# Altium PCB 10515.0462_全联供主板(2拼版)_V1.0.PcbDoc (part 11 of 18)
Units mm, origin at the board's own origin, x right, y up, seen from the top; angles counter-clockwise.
Board outline 282 x 198 mm, 2 copper layers (Top Layer, Bottom Layer); 716 components, 0 nets, 2364 pads, 1800 vias.
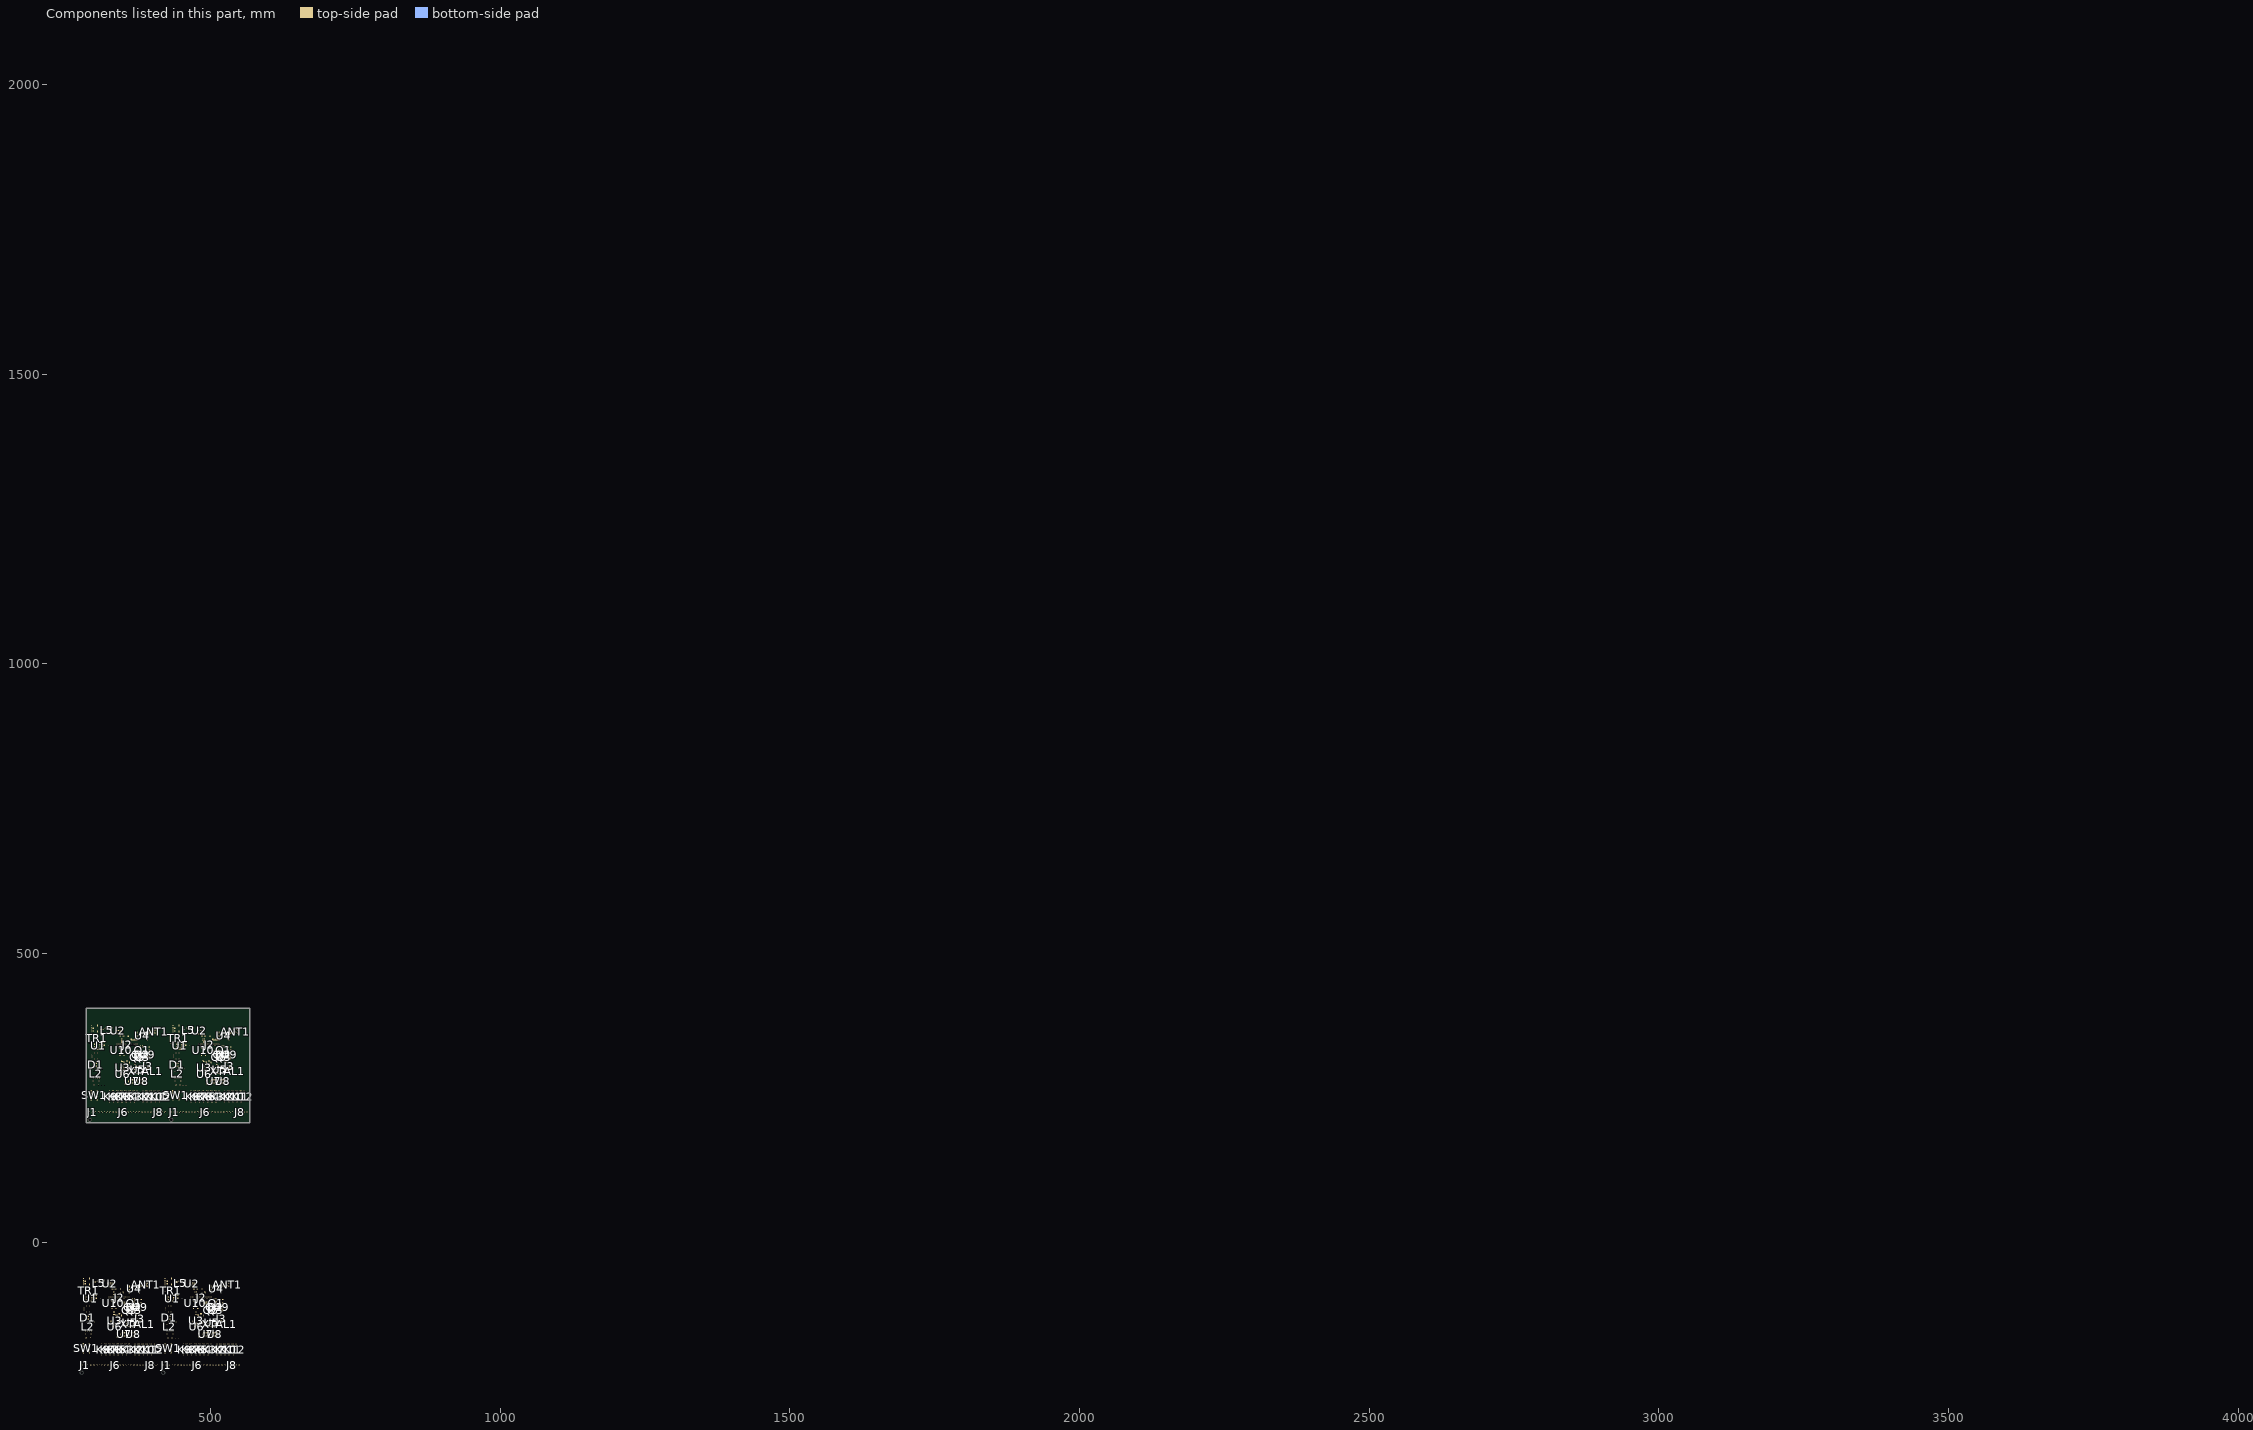
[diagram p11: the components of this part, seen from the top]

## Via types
v1: diameter 0.7, hole 0.4, Top Layer to Bottom Layer, tented both sides, 1800 vias

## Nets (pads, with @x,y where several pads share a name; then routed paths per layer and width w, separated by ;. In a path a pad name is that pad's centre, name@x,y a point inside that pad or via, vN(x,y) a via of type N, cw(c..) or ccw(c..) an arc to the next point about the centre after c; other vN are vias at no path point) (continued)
copper on no net: (continued)
  Top Layer w0.65: 500.638,-117.091 cw(c499.89,-117.091) 500.419,-117.621 cw(c500.948,-118.15) 500.948,-117.401 ; 500.684,353.257 v1@499.668,354.273 ; 501.094,331.277 501.094,334.654 ; 501.758,-118.909 503.917,-118.909 503.917,-119.63 504.327,-120.041 v1(504.581,-120.041) ; 501.758,-109.765 501.758,-112.781 501.948,-112.972 501.948,-114.591 ; 501.76,-112.861 cw(c501.307,-113.315) 501.948,-113.315 ; 501.774,-114.354 ccw(c501.353,-113.933) 501.948,-113.933 ccw(c502.543,-113.933) 502.122,-114.354 ; 502.031,350.209 ccw(c502.031,351.385) 502.862,350.554 ; v1(502.081,308.486) 502.081,311.855 501.674,312.262 500.607,312.262 ; 502.081,311.093 500.912,312.262 500.607,312.262 ; 502.22,352.432 cw(c502.22,351.523) 502.862,352.166 ; 502.373,353.346 cw(c501.251,352.223) 502.838,352.223 ; 502.462,350.534 502.92,350.534 ; 502.745,334.654 v1(503.589,334.654) ; 502.84,350.514 cw(c502.462,350.597) 502.462,350.209 500.43,350.209 ; 503.279,-107.306 ccw(c502.553,-106.58) 503.579,-106.58 ccw(c504.605,-106.58) 503.88,-107.306 ccw(c504.605,-106.58) 504.605,-107.606 ccw(c504.605,-108.632) 503.88,-107.907 ; 503.679,-112.797 cw(c503.258,-113.218) 503.853,-113.218 cw(c504.448,-113.218) 504.027,-112.797 ; 503.73,-105.271 cw(c505.343,-106.884) 505.343,-104.603 ; 503.853,-114.528 503.853,-112.559 ; 504.105,-119.819 ccw(c504.581,-119.342) v1@504.581,-120.016 ; 504.29,352.14 504.772,352.622 508.609,352.622 509.016,352.216 ; 504.347,352.12 cw(c505.56,350.908) 505.56,352.622 ; 504.581,-128.806 v1(504.581,-127.28) ; 504.61,331.32 504.61,334.654 ; 504.634,-109.84 ccw(c504.105,-109.311) 504.853,-109.311 ccw(c505.601,-109.311) 505.072,-109.84 ; 504.853,-110.059 504.853,-107.749 ; 505.343,-103.658 503.579,-105.422 503.579,-107.606 506.246,-107.606 ; 505.568,-116.75 505.568,-118.909 507.854,-118.909 ; 505.708,350.534 501.319,350.534 ; 505.789,350.616 503.002,350.616 502.92,350.534 ; 505.946,-107.907 ccw(c505.22,-108.632) 505.22,-107.606 ccw(c505.22,-106.58) 505.946,-107.306 ; v1(506.291,-128.11) 507.107,-127.294 v1(507.107,-126.264) ; v1(507.121,-101.118) 508.201,-101.118 ; 507.87,-112.797 cw(c507.449,-113.218) 508.044,-113.218 cw(c508.639,-113.218) 508.218,-112.797 ; 507.93,352.622 cw(c507.93,351.169) 508.958,352.197 ; 508.044,-112.559 508.044,-113.631 509.044,-114.631 511.623,-114.631 511.727,-114.528 ; 508.079,331.277 508.079,334.654 ; 508.137,-102.039 ccw(c509.012,-102.039) 508.393,-102.658 ; 508.137,-101.118 508.137,-102.814 508.219,-102.896 ; 508.734,-114.631 ccw(c507.986,-114.631) 508.515,-114.102 ccw(c509.044,-113.573) 509.044,-114.321 ; 508.95,-105.615 cw(c507.198,-107.367) 509.675,-107.367 ; 509.073,352.197 cw(c509.723,351.548) 509.723,352.465 ; 509.169,-105.396 509.675,-105.902 509.675,-107.606 ; 509.263,-114.851 cw(c509.792,-115.38) 509.792,-114.631 cw(c509.792,-113.883) 509.263,-114.412 ; 509.265,352.465 512.495,352.465 ; 509.375,-107.306 ccw(c508.649,-106.58) 509.675,-106.58 ccw(c510.701,-106.58) 509.976,-107.306 ; 509.41,-105.156 cw(c508.768,-105.797) 509.675,-105.797 ; 509.706,352.465 cw(c509.706,351.548) 510.355,352.197 ; 509.832,-101.176 cw(c509.019,-101.989) 510.169,-101.989 ; 509.852,-101.118 510.169,-101.435 510.169,-102.896 ; 509.994,-117.131 509.994,-117.453 v1(510.804,-118.263) ; 509.995,-102.658 ccw(c509.574,-102.237) 510.169,-102.237 ccw(c510.764,-102.237) 510.343,-102.658 ; 510.179,320.434 510.179,323.852 510.179,325.376 ; 510.241,-117.195 ccw(c511.458,-117.195) v1@510.597,-118.056 ; v1@510.28,-127.28 v1(510.28,-127.153) 510.28,-126.179 510.779,-125.68 ; v1@510.28,-127.199 cw(c512.004,-127.199) 510.858,-125.911 ; 510.47,352.197 cw(c511.12,351.548) 511.12,352.465 ; 511.103,352.465 cw(c511.103,351.548) 511.752,352.197 ; 511.783,322.109 513.522,322.109 ; 511.83,322.156 511.83,323.852 ; 511.83,325.376 511.83,326.83 ; 511.867,352.197 cw(c512.517,351.548) 512.517,352.465 ; 512.932,322.109 cw(c512.932,321.373) 513.452,321.893 ; 513.373,332.158 cw(c512.41,331.195) 513.772,331.195 cw(c515.134,331.195) 514.171,332.158 ; 513.452,322.242 ccw(c512.711,322.984) 513.76,322.984 ; 513.479,328.689 cw(c512.859,328.069) 513.735,328.069 ; 513.735,317.501 cw(c515.744,317.501) 514.733,319.236 ; 513.735,317.686 513.735,318.663 514.577,319.504 ; 513.735,318.314 cw(c514.616,318.314) 514.587,319.194 ; 513.735,318.632 cw(c515.085,318.632) 514.406,319.798 ; 513.735,318.986 cw(c514.594,318.986) 514.566,319.844 ; 513.735,326.83 513.735,328.945 ; 513.735,327.857 cw(c514.911,327.857) 514.08,328.689 ; 513.76,322.137 v1(513.76,324.555) 513.76,325.393 ; v1(513.772,331.039) 513.772,332.937 ; 514.267,319.504 cw(c513.518,319.504) 514.048,318.975 cw(c514.577,318.446) 514.577,319.194 ; v1(514.614,-112.057) 515.453,-112.057 520.78,-112.057 521.616,-112.057 522.361,-112.802 522.361,-119.533 v1(522.615,-119.787) ; 515.386,317.686 517.545,317.686 517.545,316.965 517.956,316.554 v1(518.21,316.554) ; 515.386,326.83 515.386,323.814 515.577,323.624 515.577,322.004 ; 515.389,323.735 cw(c514.935,323.281) 515.577,323.281 ; 515.402,322.242 ccw(c514.982,322.663) 515.577,322.663 ccw(c516.172,322.663) 515.751,322.242 ; v1(516.457,-119.787) 516.457,-118.864 ; 516.908,329.29 ccw(c516.182,330.015) 517.208,330.015 ccw(c518.234,330.015) 517.509,329.29 ccw(c518.234,330.015) 518.234,328.989 ccw(c518.234,327.963) 517.509,328.689 ; 517.307,323.798 cw(c516.887,323.377) 517.482,323.377 cw(c518.077,323.377) 517.656,323.798 ; 517.359,331.324 cw(c518.972,329.711) 518.972,331.992 ; 517.482,322.068 517.482,324.036 ; 517.734,316.777 ccw(c518.21,317.253) v1@518.21,316.579 ; 518.003,-73.91 515.279,-73.91 514.36,-74.829 514.36,-83.465 513.695,-84.13 500.303,-84.13 498.866,-84.13 ; v1@518.006,-119.75 518.006,-118.864 ; 518.21,307.789 v1(518.21,309.315) ; 518.263,326.755 ccw(c517.733,327.284) 518.482,327.284 ccw(c519.23,327.284) 518.701,326.755 ; 518.482,326.536 518.482,328.846 ; 518.972,332.937 517.208,331.174 517.208,328.989 519.875,328.989 ; 519.196,319.845 519.196,317.686 521.482,317.686 ; 519.51,-108.253 519.51,-105.753 ; 519.51,-106.121 cw(c520.212,-106.121) 519.715,-105.624 ; 519.575,328.689 ccw(c518.849,327.963) 518.849,328.989 ccw(c518.849,330.015) 519.575,329.29 ; v1(519.92,308.486) 520.736,309.301 v1(520.736,310.331) ; v1(520.75,335.477) 521.829,335.477 ; 521.498,323.798 cw(c521.078,323.377) 521.673,323.377 cw(c522.268,323.377) 521.847,323.798 ; 521.673,324.036 521.673,322.964 522.673,321.964 525.252,321.964 525.356,322.068 ; 521.766,334.556 ccw(c522.641,334.556) 522.022,333.937 ; 521.766,335.477 521.766,333.781 521.848,333.699 ; 522.361,-119.113 ccw(c523.289,-119.113) v1@522.633,-119.769 ; 522.363,321.964 ccw(c521.614,321.964) 522.144,322.493 ccw(c522.673,323.022) 522.673,322.274 ; 522.579,330.98 cw(c520.827,329.229) 523.304,329.229 ; 522.798,331.2 523.304,330.693 523.304,328.989 ; 522.892,321.745 cw(c523.421,321.216) 523.421,321.964 cw(c523.421,322.712) 522.892,322.183 ; 523.004,329.29 ccw(c522.278,330.015) 523.304,330.015 ccw(c524.33,330.015) 523.605,329.29 ; 523.038,331.44 cw(c522.396,330.798) 523.304,330.798 ; 523.461,335.42 cw(c522.647,334.606) 523.798,334.606 ; 523.48,335.477 523.798,335.16 523.798,333.699 ; 523.623,319.464 523.623,319.143 v1(524.433,318.332) ; 523.624,333.937 ccw(c523.203,334.358) 523.798,334.358 ccw(c524.393,334.358) 523.972,333.937 ; v1@523.631,-74.482 526.033,-74.482 ; 523.869,319.401 ccw(c525.087,319.401) v1@524.226,318.539 ; v1@523.909,309.315 v1(523.909,309.442) 523.909,310.417 524.407,310.916 ; v1@523.909,309.396 cw(c525.633,309.396) 524.487,310.684 ; v1(528.243,324.539) 529.082,324.539 534.408,324.539 535.245,324.539 535.99,323.793 535.99,317.062 v1(536.244,316.808) ; v1(530.086,316.808) 530.086,317.731 ; 531.632,362.685 528.908,362.685 527.989,361.766 527.989,353.13 527.324,352.465 513.932,352.465 512.495,352.465 ; v1@531.634,316.846 531.634,317.731 ; 533.138,328.342 533.138,330.843 ; 533.138,330.475 cw(c533.841,330.475) 533.344,330.971 ; 535.99,317.482 ccw(c536.917,317.482) v1@536.262,316.826 ; v1@537.26,362.114 539.661,362.114 ; 292.017,-64.923 292.017,-64.288 ; 292.017,-64.923 292.017,-65.367 293.217,-66.568 295.509,-66.568 ; 292.144,-69.431 292.969,-69.431 ; 292.144,-69.431 292.461,-69.114 ; 292.366,-70.035 295.604,-70.035 296.208,-69.431 ; 292.366,-70.035 292.969,-69.431 ; 292.461,-69.114 295.89,-69.114 296.208,-69.431 ; 292.969,-69.431 296.208,-69.431 ; 297.083,-66.549 297.186,-66.549 297.668,-66.066 ; 297.083,-66.549 299.827,-66.549 ; 299.827,-66.549 303.487,-66.549 304.096,-65.939 301.478,-65.939 ; 299.827,-66.549 300.081,-66.295 300.081,-65.685 ; 300.081,-65.685 v1(300.589,-65.177) ; 300.589,-66.51 300.907,-66.51 301.478,-65.939 ; 300.589,-66.51 v1(300.589,-65.177) ; 300.589,-66.51 300.97,-66.129 300.97,-65.177 v1(300.589,-65.177) ; v1(300.589,-65.177) v1(301.224,-65.177) 301.478,-65.431 301.478,-65.939 ; 305.645,371.672 305.645,372.307 ; 305.645,371.672 305.645,371.228 306.846,370.027 309.138,370.027 ; 305.772,367.164 306.598,367.164 ; 305.772,367.164 306.09,367.481 ; 305.995,366.561 309.233,366.561 309.836,367.164 ; 305.995,366.561 306.598,367.164 ; 306.09,367.481 309.519,367.481 309.836,367.164 ; 306.598,367.164 309.836,367.164 ; 308.504,-71.613 308.504,-73.022 308.971,-73.489 ; 308.504,-71.613 309.86,-70.257 314.178,-70.257 314.813,-70.892 314.813,-74.381 315.655,-75.223 ; 308.971,-73.489 309.041,-73.489 310.178,-72.352 ; 308.971,-65.939 308.971,-67.717 310.114,-68.86 313.924,-68.86 ; 310.712,370.047 310.814,370.047 311.297,370.529 ; 310.712,370.047 313.456,370.047 ; 312.4,-67.844 312.654,-67.844 315.575,-64.923 315.655,-64.923 ; 313.456,370.047 317.115,370.047 317.725,370.656 315.107,370.656 ; 313.456,370.047 313.71,370.301 313.71,370.91 v1(314.218,371.418) ; 313.924,-68.86 314.559,-68.86 314.813,-68.606 314.813,-66.574 ; 314.218,370.085 314.535,370.085 315.107,370.656 ; 314.218,370.085 v1(314.218,371.418) ; 314.218,370.085 314.599,370.466 314.599,371.418 v1(314.218,371.418) ; v1(314.218,371.418) v1(314.853,371.418) 315.107,371.164 315.107,370.656 ; 314.813,-66.574 314.813,-65.765 315.655,-64.923 ; 315.655,-75.223 316.578,-75.223 ; 315.655,-75.223 315.816,-75.223 317.099,-73.94 ; 315.655,-75.223 315.655,-74.241 316.21,-73.686 316.21,-72.162 316.845,-71.527 320.02,-71.527 ; 315.655,-75.223 315.655,-72.543 ; 315.655,-72.543 315.655,-71.955 316.668,-70.942 321.834,-70.942 ; 315.655,-66.248 ccw(c315.655,-67.187) 314.991,-66.523 cw(c315.655,-67.187) 315.655,-66.248 ; 315.655,-64.923 315.655,-68.559 316.374,-69.278 v1(319.893,-69.278) ; 315.655,-64.923 315.655,-66.019 316.083,-66.447 ; 316.083,-66.447 316.083,-68.225 316.591,-68.733 320.872,-68.733 ; 316.578,-75.223 317.099,-74.702 317.099,-73.94 ; 320.02,-71.527 320.655,-72.162 ; 320.02,-71.527 321.036,-71.527 ; 320.655,-72.162 322.243,-73.749 ; 321.036,-71.527 321.249,-71.527 ; 321.249,-71.527 321.834,-70.942 ; 322.133,364.983 322.133,363.573 322.6,363.106 ; 322.133,364.983 323.489,366.338 327.807,366.338 328.442,365.703 328.442,362.214 329.284,361.372 ; 322.243,-73.749 322.243,-130.157 322.667,-130.582 333.021,-130.582 ; 322.6,363.106 322.67,363.106 323.806,364.243 ; 322.6,370.656 322.6,368.878 323.743,367.735 327.553,367.735 ; 324.581,-95.795 324.581,-93.255 324.973,-93.648 324.973,-94.387 ; 324.581,-95.795 327.121,-95.795 327.121,-93.255 ; 324.581,-95.795 325.1,-95.276 326.116,-95.276 ; 324.973,-94.895 cw(c324.507,-94.895) 324.545,-95.36 ccw(c324.507,-94.895) 324.973,-94.895 ; 324.973,-94.895 324.973,-94.387 ; 326.029,368.751 326.283,368.751 329.204,371.672 329.284,371.672 ; 327.553,367.735 328.188,367.735 328.442,367.989 328.442,370.021 ; 328.442,370.021 328.442,370.83 329.284,371.672 ; 329.284,361.372 330.207,361.372 ; 329.284,361.372 329.445,361.372 330.728,362.655 ; 329.284,361.372 329.284,362.354 329.839,362.909 329.839,364.433 330.474,365.068 333.649,365.068 ; 329.284,361.372 329.284,364.052 ; 329.284,364.052 329.284,364.64 330.297,365.653 335.463,365.653 ; 329.284,370.347 ccw(c329.284,369.408) 328.62,370.072 cw(c329.284,369.408) 329.284,370.347 ; 329.284,371.672 329.284,368.036 330.003,367.318 v1(333.522,367.318) ; 329.284,371.672 329.284,370.576 329.712,370.148 ; 329.474,-112.802 331.323,-112.802 332.226,-111.899 ; 329.474,-112.802 329.474,-112.985 330.307,-113.818 331.323,-113.818 ; 329.474,-112.802 329.672,-112.802 330.18,-112.294 331.069,-112.294 ; 329.712,370.148 329.712,368.37 330.22,367.862 334.501,367.862 ; 330.207,361.372 330.728,361.893 330.728,362.655 ; 331.069,-112.294 331.704,-111.659 331.704,-108.865 ; 331.323,-113.818 332.238,-114.732 332.238,-123.393 ; 331.704,-108.865 331.704,-93.752 ; 332.238,-125.4 332.238,-123.393 ; 332.238,-125.4 332.822,-125.985 337.977,-125.985 ; 332.238,-125.4 332.238,-126.035 332.847,-126.645 ; 332.238,-123.393 332.238,-123.749 332.593,-124.105 332.593,-125.248 ; 332.847,-126.645 337.317,-126.645 ; 332.847,-126.645 337.317,-126.645 ; 333.649,365.068 334.284,364.433 ; 333.649,365.068 334.665,365.068 ; 333.889,-123.393 333.889,-114.301 335.387,-112.802 ; 333.889,-123.393 333.889,-124.003 334.219,-124.334 337.977,-124.334 ; 333.889,-88.849 333.889,-91.745 334.244,-92.101 ; 333.889,-88.849 334.361,-88.376 334.361,-86.777 333.889,-87.25 333.889,-88.849 ; 334.244,-95.022 334.244,-92.101 ; 334.244,-92.101 334.741,-92.598 334.741,-93.255 ; 334.284,364.433 335.871,362.846 ; 334.478,-93.604 cw(c334.078,-94.133) 334.741,-94.133 ; 334.478,-93.604 cw(c334.078,-94.133) 334.741,-94.133 ; 334.478,-93.604 cw(c334.078,-94.133) 334.741,-94.133 ; 334.665,365.068 334.878,365.068 ; 334.741,-95.795 337.281,-95.795 ; 334.741,-95.795 334.741,-94.641 ; 334.741,-94.641 334.741,-94.133 ; 334.741,-94.133 cw(c335.404,-94.133) 335.004,-93.604 ; 334.741,-94.133 cw(c335.404,-94.133) 335.004,-93.604 ; 334.741,-94.133 cw(c335.404,-94.133) 335.004,-93.604 ; 334.741,-94.133 334.741,-93.255 ; 334.741,-93.255 337.281,-93.255 ; 334.878,365.068 335.463,365.653 ; 335.006,-104.293 335.006,-108.23 335.006,-111.334 336.474,-112.802 ; 335.05,-96.104 cw(c335.796,-96.85) 335.796,-95.795 cw(c335.796,-94.74) 335.05,-95.486 ; 335.387,-112.802 336.474,-112.802 ; 335.871,362.846 335.871,306.438 336.296,306.013 346.65,306.013 ; 336.403,-92.736 336.403,-88.545 336.784,-88.164 ; 336.784,-88.164 341.61,-83.338 341.61,-81.306 343.205,-79.711 344.023,-79.711 ; 336.911,-96.292 337.281,-95.922 337.281,-95.795 ; 337.281,-95.795 337.281,-93.255 ; 337.317,-126.645 337.977,-125.985 ; 337.977,-125.985 340.823,-125.985 342.174,-127.336 342.174,-127.605 ; 337.977,-125.985 338.41,-125.985 338.88,-126.454 ; 337.977,-124.334 341.255,-124.334 342.174,-123.414 ; 337.977,-124.334 338.207,-124.334 338.562,-123.978 ; 338.21,340.8 338.21,343.34 338.602,342.948 338.602,342.208 ; 338.21,340.8 340.75,340.8 340.75,343.34 ; 338.21,340.8 338.729,341.319 339.745,341.319 ; 338.562,-123.978 339.578,-123.978 ; 338.602,341.7 338.602,342.208 ; 338.88,-126.454 339.07,-126.645 ; 339.07,-126.645 340.34,-127.915 ; 339.07,-126.645 339.832,-126.645 ; 339.578,-123.978 339.959,-123.978 ; 339.959,-123.978 340.464,-123.978 ; 339.959,-123.978 340.464,-123.978 ; 340.464,-123.978 342.174,-122.268 ; 340.75,342.716 340.75,343.34 ; v1(341.494,-87.518) 341.864,-87.148 ; v1(341.494,-87.518) 341.494,-87.54 341.928,-87.973 ; v1(341.494,-87.518) 342.753,-86.259 ; 341.864,-87.148 v1@342.301,-86.711 ; 341.928,-87.973 v1(342.245,-88.291) ; 341.928,-87.973 343.96,-87.973 344.023,-87.91 ; 342.174,-127.605 343.795,-125.985 345.978,-125.985 ; 342.174,-123.414 342.174,-122.268 ; 342.174,-122.268 344.24,-124.334 345.978,-124.334 ; v1(342.245,-88.291) 343.642,-88.291 ; v1(342.245,-88.291) v1(340.721,-88.291) v1@342.301,-86.711 ; v1@342.301,-86.711 ccw(c342.722,-87.132) 342.264,-87.513 cw(c342.722,-87.132) v1@342.301,-86.711 ; v1@342.301,-86.711 344.023,-86.711 344.023,-87.91 ; 342.654,-83.183 342.654,-81.08 ; 342.654,-81.08 344.023,-79.711 ; 343.103,323.793 344.952,323.793 345.855,324.696 ; 343.103,323.793 343.103,323.61 343.936,322.777 344.952,322.777 ; 343.103,323.793 343.301,323.793 343.809,324.301 344.698,324.301 ; 343.642,-88.291 344.023,-87.91 ; 343.642,-88.291 343.896,-88.291 345.42,-86.767 ; 344.023,-79.711 344.023,-83.719 344.714,-84.41 357.15,-84.41 357.431,-84.13 357.866,-84.13 ; 344.023,-79.711 345.039,-80.727 ; 344.698,324.301 345.333,324.936 345.333,327.73 ; 344.952,322.777 345.866,321.863 345.866,313.202 ; v1@345.039,-82.322 345.039,-80.727 ; 345.333,327.73 345.333,342.843 ; 345.42,-86.767 347.585,-86.767 348.291,-86.061 ; 345.42,-86.767 345.801,-86.386 ; 345.547,-86.061 346.69,-86.061 ; 345.801,-86.386 346.126,-86.061 346.69,-86.061 ; 345.866,311.195 345.866,313.202 ; 345.866,311.195 346.45,310.611 351.606,310.611 ; 345.866,311.195 345.866,310.56 346.476,309.95 ; 345.866,313.202 345.866,312.846 346.222,312.49 346.222,311.347 ; 346.476,309.95 350.945,309.95 ; 346.476,309.95 350.945,309.95 ; 347.517,313.202 347.517,322.295 349.016,323.793 ; 347.517,313.202 347.517,312.592 347.847,312.262 351.606,312.262 ; 347.517,347.746 347.517,344.85 347.873,344.494 ; 347.517,347.746 347.99,348.219 347.99,349.818 347.517,349.346 347.517,347.746 ; 347.873,341.573 347.873,344.494 ; 347.873,344.494 348.37,343.998 348.37,343.34 ; 348.106,342.991 cw(c347.707,342.463) 348.37,342.463 ; 348.106,342.991 cw(c347.707,342.463) 348.37,342.463 ; 348.106,342.991 cw(c347.707,342.463) 348.37,342.463 ; 348.37,340.8 350.91,340.8 ; 348.37,340.8 348.37,341.954 ; 348.37,341.954 348.37,342.462 ; 348.37,342.463 cw(c349.032,342.463) 348.633,342.991 ; 348.37,342.463 cw(c349.032,342.463) 348.633,342.991 ; 348.37,342.463 cw(c349.032,342.463) 348.633,342.991 ; 348.37,342.462 348.37,343.34 ; 348.37,343.34 350.91,343.34 ; 348.635,332.302 348.635,328.365 348.635,325.261 350.103,323.793 ; 348.679,340.491 cw(c349.425,339.745) 349.425,340.8 cw(c349.425,341.855) 348.679,341.109 ; 349.016,323.793 350.103,323.793 ; 350.032,343.859 350.032,348.05 350.413,348.431 ; 350.413,348.431 355.239,353.257 355.239,355.289 356.834,356.884 357.652,356.884 ; 350.54,340.303 350.91,340.673 350.91,340.8 ; 350.91,340.8 350.91,343.34 ; 350.945,309.95 351.606,310.611 ; 351.606,310.611 354.451,310.611 355.803,309.26 355.803,308.99 ; 351.606,310.611 352.038,310.611 352.508,310.141 ; 351.606,312.262 354.883,312.262 355.803,313.181 ; 351.606,312.262 351.835,312.262 352.191,312.617 ; 352.191,312.617 353.207,312.617 ; 352.508,310.141 352.699,309.95 ; 352.699,309.95 353.969,308.68 ; 352.699,309.95 353.461,309.95 ; 353.207,312.617 353.588,312.617 ; 353.588,312.617 354.092,312.617 ; 353.588,312.617 354.092,312.617 ; 354.092,312.617 355.803,314.328 ; v1(355.122,349.077) 355.493,349.447 ; v1(355.122,349.077) 355.122,349.056 355.556,348.622 ; v1(355.122,349.077) 356.382,350.336 ; 355.493,349.447 v1@355.93,349.884 ; 355.556,348.622 v1(355.874,348.304) ; 355.556,348.622 357.588,348.622 357.652,348.685 ; 355.803,308.99 357.423,310.611 359.607,310.611 ; 355.803,313.181 355.803,314.328 ; 355.803,314.328 357.869,312.262 359.607,312.262 ; v1(355.874,348.304) 357.271,348.304 ; v1(355.874,348.304) v1(354.35,348.304) v1@355.93,349.884 ; v1@355.93,349.884 ccw(c356.351,349.463) 355.893,349.082 cw(c356.351,349.463) v1@355.93,349.884 ; v1@355.93,349.884 357.652,349.884 357.652,348.685 ; 356.283,353.412 356.283,355.515 ; 356.283,355.515 357.652,356.884 ; 357.24,-84.398 cw(c357.866,-84.996) 357.866,-84.13 ; 357.24,-84.398 cw(c357.866,-84.996) 357.866,-84.13 ; 357.24,-84.398 cw(c357.866,-84.996) 357.866,-84.13 ; 357.271,348.304 357.652,348.685 ; 357.271,348.304 357.525,348.304 359.049,349.828 ; 357.652,356.884 357.652,352.876 358.343,352.185 370.779,352.185 371.059,352.465 371.495,352.465 ; 357.652,356.884 358.668,355.868 ; v1@358.668,354.273 358.668,355.868 ; 359.049,349.828 361.214,349.828 361.92,350.534 ; 359.049,349.828 359.43,350.209 ; 359.176,350.534 360.319,350.534 ; 359.43,350.209 359.755,350.534 360.319,350.534 ; 370.869,352.198 cw(c371.495,351.599) 371.495,352.465 ; 370.869,352.198 cw(c371.495,351.599) 371.495,352.465 ; 370.869,352.198 cw(c371.495,351.599) 371.495,352.465 ; 433.017,-64.923 433.017,-64.288 ; 433.017,-64.923 433.017,-65.367 434.217,-66.568 436.509,-66.568 ; 433.144,-69.431 433.969,-69.431 ; 433.144,-69.431 433.461,-69.114 ; 433.366,-70.035 436.604,-70.035 437.208,-69.431 ; 433.366,-70.035 433.969,-69.431 ; 433.461,-69.114 436.89,-69.114 437.208,-69.431 ; 433.969,-69.431 437.208,-69.431 ; 438.083,-66.549 438.186,-66.549 438.668,-66.066 ; 438.083,-66.549 440.827,-66.549 ; 440.827,-66.549 444.487,-66.549 445.096,-65.939 442.478,-65.939 ; 440.827,-66.549 441.081,-66.295 441.081,-65.685 ; 441.081,-65.685 v1(441.589,-65.177) ; 441.589,-66.51 441.907,-66.51 442.478,-65.939 ; 441.589,-66.51 v1(441.589,-65.177) ; 441.589,-66.51 441.97,-66.129 441.97,-65.177 v1(441.589,-65.177) ; v1(441.589,-65.177) v1(442.224,-65.177) 442.478,-65.431 442.478,-65.939 ; 446.645,371.672 446.645,372.307 ; 446.645,371.672 446.645,371.228 447.846,370.027 450.138,370.027 ; 446.772,367.164 447.598,367.164 ; 446.772,367.164 447.09,367.481 ; 446.995,366.561 450.233,366.561 450.836,367.164 ; 446.995,366.561 447.598,367.164 ; 447.09,367.481 450.519,367.481 450.836,367.164 ; 447.598,367.164 450.836,367.164 ; 449.504,-71.613 449.504,-73.022 449.971,-73.489 ; 449.504,-71.613 450.86,-70.257 455.178,-70.257 455.813,-70.892 455.813,-74.381 456.655,-75.223 ; 449.971,-73.489 450.041,-73.489 451.178,-72.352 ; 449.971,-65.939 449.971,-67.717 451.114,-68.86 454.924,-68.86 ; 451.712,370.047 451.814,370.047 452.297,370.529 ; 451.712,370.047 454.456,370.047 ; 453.4,-67.844 453.654,-67.844 456.575,-64.923 456.655,-64.923 ; 454.456,370.047 458.115,370.047 458.725,370.656 456.107,370.656 ; 454.456,370.047 454.71,370.301 454.71,370.91 v1(455.218,371.418) ; 454.924,-68.86 455.559,-68.86 455.813,-68.606 455.813,-66.574 ; 455.218,370.085 455.535,370.085 456.107,370.656 ; 455.218,370.085 v1(455.218,371.418) ; 455.218,370.085 455.599,370.466 455.599,371.418 v1(455.218,371.418) ; v1(455.218,371.418) v1(455.853,371.418) 456.107,371.164 456.107,370.656 ; 455.813,-66.574 455.813,-65.765 456.655,-64.923 ; 456.655,-75.223 457.578,-75.223 ; 456.655,-75.223 456.816,-75.223 458.099,-73.94 ; 456.655,-75.223 456.655,-74.241 457.21,-73.686 457.21,-72.162 457.845,-71.527 461.02,-71.527 ; 456.655,-75.223 456.655,-72.543 ; 456.655,-72.543 456.655,-71.955 457.668,-70.942 462.834,-70.942 ; 456.655,-66.248 ccw(c456.655,-67.187) 455.991,-66.523 cw(c456.655,-67.187) 456.655,-66.248 ; 456.655,-64.923 456.655,-68.559 457.374,-69.278 v1(460.893,-69.278) ; 456.655,-64.923 456.655,-66.019 457.083,-66.447 ; 457.083,-66.447 457.083,-68.225 457.591,-68.733 461.872,-68.733 ; 457.578,-75.223 458.099,-74.702 458.099,-73.94 ; 461.02,-71.527 461.655,-72.162 ; 461.02,-71.527 462.036,-71.527 ; 461.655,-72.162 463.243,-73.749 ; 462.036,-71.527 462.249,-71.527 ; 462.249,-71.527 462.834,-70.942 ; 463.133,364.983 463.133,363.573 463.6,363.106 ; 463.133,364.983 464.489,366.338 468.807,366.338 469.442,365.703 469.442,362.214 470.284,361.372 ; 463.243,-73.749 463.243,-130.157 463.667,-130.582 474.021,-130.582 ; 463.6,363.106 463.67,363.106 464.806,364.243 ; 463.6,370.656 463.6,368.878 464.743,367.735 468.553,367.735 ; 465.581,-95.795 465.581,-93.255 465.973,-93.648 465.973,-94.387 ; 465.581,-95.795 468.121,-95.795 468.121,-93.255 ; 465.581,-95.795 466.1,-95.276 467.116,-95.276 ; 465.973,-94.895 cw(c465.507,-94.895) 465.545,-95.36 ccw(c465.507,-94.895) 465.973,-94.895 ; 465.973,-94.895 465.973,-94.387 ; 467.029,368.751 467.283,368.751 470.204,371.672 470.284,371.672 ; 468.121,-93.879 468.121,-93.255 ; 468.553,367.735 469.188,367.735 469.442,367.989 469.442,370.021 ; 469.442,370.021 469.442,370.83 470.284,371.672 ; 470.284,361.372 471.207,361.372 ; 470.284,361.372 470.445,361.372 471.728,362.655 ; 470.284,361.372 470.284,362.354 470.839,362.909 470.839,364.433 471.474,365.068 474.649,365.068 ; 470.284,361.372 470.284,364.052 ; 470.284,364.052 470.284,364.64 471.297,365.653 476.463,365.653 ; 470.284,370.347 ccw(c470.284,369.408) 469.62,370.072 cw(c470.284,369.408) 470.284,370.347 ; 470.284,371.672 470.284,368.036 471.003,367.318 v1(474.522,367.318) ; 470.284,371.672 470.284,370.576 470.712,370.148 ; 470.474,-112.802 472.323,-112.802 473.226,-111.899 ; 470.474,-112.802 470.474,-112.985 471.307,-113.818 472.323,-113.818 ; 470.474,-112.802 470.672,-112.802 471.18,-112.294 472.069,-112.294 ; 470.712,370.148 470.712,368.37 471.22,367.862 475.501,367.862 ; 471.207,361.372 471.728,361.893 471.728,362.655 ; 472.069,-112.294 472.704,-111.659 472.704,-108.865 ; 472.323,-113.818 473.238,-114.732 473.238,-123.393 ; 472.704,-108.865 472.704,-93.752 ; 473.238,-125.4 473.238,-123.393 ; 473.238,-125.4 473.822,-125.985 478.977,-125.985 ; 473.238,-125.4 473.238,-126.035 473.847,-126.645 ; 473.238,-123.393 473.238,-123.749 473.593,-124.105 473.593,-125.248 ; 473.847,-126.645 478.317,-126.645 ; 473.847,-126.645 478.317,-126.645 ; 474.649,365.068 475.284,364.433 ; 474.649,365.068 475.665,365.068 ; 474.889,-123.393 474.889,-114.301 476.387,-112.802 ; 474.889,-123.393 474.889,-124.003 475.219,-124.334 478.977,-124.334 ; 474.889,-88.849 474.889,-91.745 475.244,-92.101 ; 474.889,-88.849 475.361,-88.376 475.361,-86.777 474.889,-87.25 474.889,-88.849 ; 475.244,-95.022 475.244,-92.101 ; 475.244,-92.101 475.741,-92.598 475.741,-93.255 ; 475.284,364.433 476.871,362.846 ; 475.478,-93.604 cw(c475.078,-94.133) 475.741,-94.133 ; 475.478,-93.604 cw(c475.078,-94.133) 475.741,-94.133 ; 475.478,-93.604 cw(c475.078,-94.133) 475.741,-94.133 ; 475.665,365.068 475.878,365.068 ; 475.741,-95.795 478.281,-95.795 ; 475.741,-95.795 475.741,-94.641 ; 475.741,-94.641 475.741,-94.133 ; 475.741,-94.133 cw(c476.404,-94.133) 476.004,-93.604 ; 475.741,-94.133 cw(c476.404,-94.133) 476.004,-93.604 ; 475.741,-94.133 cw(c476.404,-94.133) 476.004,-93.604 ; 475.741,-94.133 475.741,-93.255 ; 475.741,-93.255 478.281,-93.255 ; 475.878,365.068 476.463,365.653 ; 476.006,-104.293 476.006,-108.23 476.006,-111.334 477.474,-112.802 ; 476.05,-96.104 cw(c476.796,-96.85) 476.796,-95.795 cw(c476.796,-94.74) 476.05,-95.486 ; 476.387,-112.802 477.474,-112.802 ; 476.871,362.846 476.871,306.438 477.296,306.013 487.65,306.013 ; 477.403,-92.736 477.403,-88.545 477.784,-88.164 ; 477.784,-88.164 482.61,-83.338 482.61,-81.306 484.205,-79.711 485.023,-79.711 ; 477.911,-96.292 478.281,-95.922 478.281,-95.795 ; 478.281,-95.795 478.281,-93.255 ; 478.317,-126.645 478.977,-125.985 ; 478.977,-125.985 481.823,-125.985 483.174,-127.336 483.174,-127.605 ; 478.977,-125.985 479.41,-125.985 479.88,-126.454 ; 478.977,-124.334 482.255,-124.334 483.174,-123.414 ; 478.977,-124.334 479.207,-124.334 479.562,-123.978 ; 479.21,340.8 479.21,343.34 479.602,342.948 479.602,342.208 ; 479.21,340.8 481.75,340.8 481.75,343.34 ; 479.21,340.8 479.729,341.319 480.745,341.319 ; 479.562,-123.978 480.578,-123.978 ; 479.602,341.7 479.602,342.208 ; 479.88,-126.454 480.07,-126.645 ; 480.07,-126.645 481.34,-127.915 ; 480.07,-126.645 480.832,-126.645 ; 480.578,-123.978 480.959,-123.978 ; 480.959,-123.978 481.464,-123.978 ; 480.959,-123.978 481.464,-123.978 ; 481.464,-123.978 483.174,-122.268 ; v1(482.494,-87.518) 482.864,-87.148 ; v1(482.494,-87.518) 482.494,-87.54 482.928,-87.973 ; v1(482.494,-87.518) 483.753,-86.259 ; 482.864,-87.148 v1@483.301,-86.711 ; 482.928,-87.973 v1(483.245,-88.291) ; 482.928,-87.973 484.96,-87.973 485.023,-87.91 ; 483.174,-127.605 484.795,-125.985 486.978,-125.985 ; 483.174,-123.414 483.174,-122.268 ; 483.174,-122.268 485.24,-124.334 486.978,-124.334 ; v1(483.245,-88.291) 484.642,-88.291 ; v1(483.245,-88.291) v1(481.721,-88.291) v1@483.301,-86.711 ; v1@483.301,-86.711 ccw(c483.722,-87.132) 483.264,-87.513 cw(c483.722,-87.132) v1@483.301,-86.711 ; v1@483.301,-86.711 485.023,-86.711 485.023,-87.91 ; 483.654,-83.183 483.654,-81.08 ; 483.654,-81.08 485.023,-79.711 ; 484.103,323.793 485.952,323.793 486.855,324.696 ; 484.103,323.793 484.103,323.61 484.936,322.777 485.952,322.777 ; 484.103,323.793 484.301,323.793 484.809,324.301 485.698,324.301 ; 484.642,-88.291 485.023,-87.91 ; 484.642,-88.291 484.896,-88.291 486.42,-86.767 ; 485.023,-79.711 485.023,-83.719 485.714,-84.41 498.15,-84.41 498.431,-84.13 498.866,-84.13 ; 485.023,-79.711 486.039,-80.727 ; 485.698,324.301 486.333,324.936 486.333,327.73 ; 485.952,322.777 486.866,321.863 486.866,313.202 ; v1@486.039,-82.322 486.039,-80.727 ; 486.333,327.73 486.333,342.843 ; 486.42,-86.767 488.585,-86.767 489.291,-86.061 ; 486.42,-86.767 486.801,-86.386 ; 486.547,-86.061 487.69,-86.061 ; 486.801,-86.386 487.126,-86.061 487.69,-86.061 ; 486.866,311.195 486.866,313.202 ; 486.866,311.195 487.45,310.611 492.606,310.611 ; 486.866,311.195 486.866,310.56 487.476,309.95 ; 486.866,313.202 486.866,312.846 487.222,312.49 487.222,311.347 ; 487.476,309.95 491.945,309.95 ; 487.476,309.95 491.945,309.95 ; 488.517,313.202 488.517,322.295 490.016,323.793 ; 488.517,313.202 488.517,312.592 488.847,312.262 492.606,312.262 ; 488.517,347.746 488.517,344.85 488.873,344.494 ; 488.517,347.746 488.99,348.219 488.99,349.818 488.517,349.346 488.517,347.746 ; 488.873,341.573 488.873,344.494 ; 488.873,344.494 489.37,343.998 489.37,343.34 ; 489.106,342.991 cw(c488.707,342.463) 489.37,342.463 ; 489.106,342.991 cw(c488.707,342.463) 489.37,342.463 ; 489.106,342.991 cw(c488.707,342.463) 489.37,342.463 ; 489.37,340.8 491.91,340.8 ; 489.37,340.8 489.37,341.954 ; 489.37,341.954 489.37,342.462 ; 489.37,342.463 cw(c490.032,342.463) 489.633,342.991 ; 489.37,342.463 cw(c490.032,342.463) 489.633,342.991 ; 489.37,342.463 cw(c490.032,342.463) 489.633,342.991 ; 489.37,342.462 489.37,343.34 ; 489.37,343.34 491.91,343.34 ; 489.635,332.302 489.635,328.365 489.635,325.261 491.103,323.793 ; 489.679,340.491 cw(c490.425,339.745) 490.425,340.8 cw(c490.425,341.855) 489.679,341.109 ; 490.016,323.793 491.103,323.793 ; 491.032,343.859 491.032,348.05 491.413,348.431 ; 491.413,348.431 496.239,353.257 496.239,355.289 497.834,356.884 498.652,356.884 ; 491.54,340.303 491.91,340.673 491.91,340.8 ; 491.91,340.8 491.91,343.34 ; 491.945,309.95 492.606,310.611 ; 492.606,310.611 495.451,310.611 496.803,309.26 496.803,308.99 ; 492.606,310.611 493.038,310.611 493.508,310.141 ; 492.606,312.262 495.883,312.262 496.803,313.181 ; 492.606,312.262 492.835,312.262 493.191,312.617 ; 493.191,312.617 494.207,312.617 ; 493.508,310.141 493.699,309.95 ; 493.699,309.95 494.969,308.68 ; 493.699,309.95 494.461,309.95 ; 494.207,312.617 494.588,312.617 ; 494.588,312.617 495.092,312.617 ; 494.588,312.617 495.092,312.617 ; 495.092,312.617 496.803,314.328 ; v1(496.122,349.077) 496.493,349.447 ; v1(496.122,349.077) 496.122,349.056 496.556,348.622 ; v1(496.122,349.077) 497.382,350.336 ; 496.493,349.447 v1@496.93,349.884 ; 496.556,348.622 v1(496.874,348.304) ; 496.556,348.622 498.588,348.622 498.652,348.685 ; 496.803,308.99 498.423,310.611 500.607,310.611 ; 496.803,313.181 496.803,314.328 ; 496.803,314.328 498.869,312.262 500.607,312.262 ; v1(496.874,348.304) 498.271,348.304 ; v1(496.874,348.304) v1(495.35,348.304) v1@496.93,349.884 ; v1@496.93,349.884 ccw(c497.351,349.463) 496.893,349.082 cw(c497.351,349.463) v1@496.93,349.884 ; v1@496.93,349.884 498.652,349.884 498.652,348.685 ; 497.283,353.412 497.283,355.515 ; 497.283,355.515 498.652,356.884 ; 498.24,-84.398 cw(c498.866,-84.996) 498.866,-84.13 ; 498.24,-84.398 cw(c498.866,-84.996) 498.866,-84.13 ; 498.24,-84.398 cw(c498.866,-84.996) 498.866,-84.13 ; 498.271,348.304 498.652,348.685 ; 498.271,348.304 498.525,348.304 500.049,349.828 ; 498.652,356.884 498.652,352.876 499.343,352.185 511.779,352.185 512.059,352.465 512.495,352.465 ; 498.652,356.884 499.668,355.868 ; v1@499.668,354.273 499.668,355.868 ; 500.049,349.828 502.214,349.828 502.92,350.534 ; 500.049,349.828 500.43,350.209 ; 500.176,350.534 501.319,350.534 ; 500.43,350.209 500.755,350.534 501.319,350.534 ; 511.869,352.198 cw(c512.495,351.599) 512.495,352.465 ; 511.869,352.198 cw(c512.495,351.599) 512.495,352.465 ; 511.869,352.198 cw(c512.495,351.599) 512.495,352.465 ; 331.166,-107.924 cw(c330.6,-108.872) 331.704,-108.872 ccw(c330.6,-108.872) 331.166,-107.924 ; 331.704,-108.721 cw(c332.991,-108.721) 332.081,-107.811 ccw(c332.991,-108.721) 331.704,-108.721 ; 338.174,341.236 ccw(c338.135,341.7) 338.602,341.7 cw(c338.135,341.7) 338.174,341.236 ; 344.795,328.671 cw(c344.229,327.723) 345.333,327.723 ccw(c344.229,327.723) 344.795,328.671 ; 345.333,327.874 cw(c346.62,327.874) 345.71,328.785 ccw(c346.62,327.874) 345.333,327.874 ; 472.166,-107.924 cw(c471.6,-108.872) 472.704,-108.872 ccw(c471.6,-108.872) 472.166,-107.924 ; 472.704,-108.721 cw(c473.991,-108.721) 473.081,-107.811 ccw(c473.991,-108.721) 472.704,-108.721 ; 479.174,341.236 ccw(c479.135,341.7) 479.602,341.7 cw(c479.135,341.7) 479.174,341.236 ; 485.795,328.671 cw(c485.229,327.723) 486.333,327.723 ccw(c485.229,327.723) 485.795,328.671 ; 486.333,327.874 cw(c487.62,327.874) 486.71,328.785 ccw(c487.62,327.874) 486.333,327.874
  Top Layer w0.8: 289.605,-72.543 290.481,-71.667 290.89,-71.667 ; 289.794,-75.845 290.89,-74.749 290.89,-72.683 ; 291.191,-69.114 289.605,-70.7 289.605,-71.146 ; 297.083,-68.2 292.106,-68.2 ; 297.121,-68.161 300.589,-68.161 ; 300.594,-68.195 ccw(c301.892,-66.896) 301.892,-68.733 ; 303.234,364.052 304.11,364.928 304.519,364.928 ; 303.423,360.75 304.519,361.846 304.519,363.912 ; 303.51,-72.878 303.51,-69.368 302.875,-68.733 302.621,-68.733 ; 303.51,-72.497 ccw(c305.113,-72.497) 303.98,-73.63 ; 303.51,-70.565 ccw(c307.045,-70.565) 304.545,-73.065 cw(c305.57,-72.04) 304.121,-72.04 cw(c302.673,-72.04) 303.697,-73.065 ; 304.121,-73.489 304.121,-68.836 303.447,-68.161 300.589,-68.161 ; 304.121,-69.241 303.613,-68.733 302.621,-68.733 ; 304.82,367.481 303.234,365.895 303.234,365.449 ; 304.971,-76.48 306.495,-78.004 314.432,-78.004 ; 310.712,368.396 305.734,368.396 ; 310.75,368.434 314.218,368.434 ; 313.924,-78.512 314.432,-78.004 ; 314.222,368.4 ccw(c315.521,369.699) 315.521,367.862 ; 315.337,-66.041 cw(c314.569,-66.809) 315.655,-66.809 cw(c316.742,-66.809) 315.973,-66.041 ; 315.575,-154.517 315.575,-158.014 316.718,-159.157 ; 315.655,-64.923 315.655,-67.035 317.353,-68.733 ; 316.38,-157.803 317.212,-158.635 ; 317.139,363.717 317.139,367.227 316.504,367.862 316.25,367.862 ; 317.139,364.099 ccw(c318.742,364.099) 317.608,362.965 ; 317.139,366.03 ccw(c320.674,366.03) 318.174,363.531 cw(c319.198,364.555) 317.75,364.555 cw(c316.301,364.555) 317.326,363.531 ; 317.75,363.106 317.75,367.759 317.075,368.434 314.218,368.434 ; 317.75,367.354 317.242,367.862 316.25,367.862 ; 318.599,360.115 320.123,358.591 328.061,358.591 ; 319.562,-156.032 320.514,-156.984 322.179,-156.984 ; 320.02,-155.474 321.53,-156.984 322.179,-156.984 ; 320.465,-155.918 320.671,-155.712 337.923,-155.712 ; 320.655,-155.206 322.433,-156.984 322.179,-156.984 ; 320.932,-155.483 319.639,-154.19 319.639,-79.02 318.623,-78.004 314.432,-78.004 ; 321.812,-156.363 343.642,-156.363 344.263,-156.984 ; 327.553,358.083 328.061,358.591 ; 328.966,370.554 cw(c328.197,369.786) 329.284,369.786 cw(c330.37,369.786) 329.602,370.554 ; 329.204,282.079 329.204,278.581 330.347,277.438 ; 329.284,371.672 329.284,369.56 330.982,367.862 ; 330.009,278.793 330.841,277.96 ; 333.191,280.564 334.143,279.611 335.808,279.611 ; 333.649,281.121 335.159,279.611 335.808,279.611 ; 334.093,280.677 334.3,280.884 351.552,280.884 ; 334.284,281.389 336.062,279.611 335.808,279.611 ; 334.56,281.113 333.268,282.405 333.268,357.575 332.252,358.591 328.061,358.591 ; 335.441,280.232 357.271,280.232 357.892,279.611 ; 343.642,-159.03 cw(c344.488,-159.876) 344.488,-158.68 ; 343.812,-158.86 cw(c344.364,-159.413) 344.487,-158.641 ; 343.896,-156.617 342.991,-155.712 337.923,-155.712 ; 344.028,-156.749 ccw(c344.488,-156.289) 344.488,-156.94 ; 344.488,-156.984 344.263,-156.984 ; 352.812,-85.98 352.818,-85.986 354.343,-85.986 354.387,-86.03 359.204,-86.03 359.303,-86.13 ; 357.271,277.566 cw(c358.117,276.72) 358.117,277.916 ; 357.44,277.735 cw(c357.993,277.183) 358.116,277.954 ; 357.525,279.978 356.62,280.884 351.552,280.884 ; 357.657,279.846 ccw(c358.117,280.306) 358.117,279.656 ; 358.117,279.611 357.892,279.611 ; 366.44,350.616 366.447,350.609 367.971,350.609 368.016,350.565 372.832,350.565 372.932,350.465 ; 377.003,-71.91 379.635,-71.91 ; 379.635,-71.942 379.635,-73.224 379.649,-73.237 ; 381.286,-71.942 381.427,-72.082 381.427,-73.364 ; 381.579,-71.942 387.573,-71.942 ; 390.632,364.685 393.264,364.685 ; 393.264,364.654 393.264,363.372 393.277,363.358 ; 394.915,364.654 395.055,364.513 395.055,363.231 ; 395.208,364.654 401.201,364.654 ; 430.605,-72.543 431.481,-71.667 431.89,-71.667 ; 430.794,-75.845 431.89,-74.749 431.89,-72.683 ; 432.191,-69.114 430.605,-70.7 430.605,-71.146 ; 438.083,-68.2 433.106,-68.2 ; 438.121,-68.161 441.589,-68.161 ; 441.594,-68.195 ccw(c442.892,-66.896) 442.892,-68.733 ; 444.234,364.052 445.11,364.928 445.519,364.928 ; 444.423,360.75 445.519,361.846 445.519,363.912 ; 444.51,-72.878 444.51,-69.368 443.875,-68.733 443.621,-68.733 ; 444.51,-72.497 ccw(c446.113,-72.497) 444.98,-73.63 ; 444.51,-70.565 ccw(c448.045,-70.565) 445.545,-73.065 cw(c446.57,-72.04) 445.121,-72.04 cw(c443.673,-72.04) 444.697,-73.065 ; 445.121,-73.489 445.121,-68.836 444.447,-68.161 441.589,-68.161 ; 445.121,-69.241 444.613,-68.733 443.621,-68.733 ; 445.82,367.481 444.234,365.895 444.234,365.449 ; 445.971,-76.48 447.495,-78.004 455.432,-78.004 ; 451.712,368.396 446.734,368.396 ; 451.75,368.434 455.218,368.434 ; 454.924,-78.512 455.432,-78.004 ; 455.222,368.4 ccw(c456.521,369.699) 456.521,367.862 ; 456.337,-66.041 cw(c455.569,-66.809) 456.655,-66.809 cw(c457.742,-66.809) 456.973,-66.041 ; 456.575,-154.517 456.575,-158.014 457.718,-159.157 ; 456.655,-64.923 456.655,-67.035 458.353,-68.733 ; 457.38,-157.803 458.212,-158.635 ; 458.139,363.717 458.139,367.227 457.504,367.862 457.25,367.862 ; 458.139,364.099 ccw(c459.742,364.099) 458.608,362.965 ; 458.139,366.03 ccw(c461.674,366.03) 459.174,363.531 cw(c460.198,364.555) 458.75,364.555 cw(c457.301,364.555) 458.326,363.531 ; 458.75,363.106 458.75,367.759 458.075,368.434 455.218,368.434 ; 458.75,367.354 458.242,367.862 457.25,367.862 ; 459.599,360.115 461.123,358.591 469.061,358.591 ; 460.562,-156.032 461.514,-156.984 463.179,-156.984 ; 461.02,-155.474 462.53,-156.984 463.179,-156.984 ; 461.465,-155.918 461.671,-155.712 478.923,-155.712 ; 461.655,-155.206 463.433,-156.984 463.179,-156.984 ; 461.932,-155.483 460.639,-154.19 460.639,-79.02 459.623,-78.004 455.432,-78.004 ; 462.812,-156.363 484.642,-156.363 485.263,-156.984 ; 468.553,358.083 469.061,358.591 ; 469.966,370.554 cw(c469.197,369.786) 470.284,369.786 cw(c471.37,369.786) 470.602,370.554 ; 470.204,282.079 470.204,278.581 471.347,277.438 ; 470.284,371.672 470.284,369.56 471.982,367.862 ; 471.009,278.793 471.841,277.96 ; 474.191,280.564 475.143,279.611 476.808,279.611 ; 474.649,281.121 476.159,279.611 476.808,279.611 ; 475.093,280.677 475.3,280.884 492.552,280.884 ; 475.284,281.389 477.062,279.611 476.808,279.611 ; 475.56,281.113 474.268,282.405 474.268,357.575 473.252,358.591 469.061,358.591 ; 476.441,280.232 498.271,280.232 498.892,279.611 ; 484.642,-159.03 cw(c485.488,-159.876) 485.488,-158.68 ; 484.812,-158.86 cw(c485.364,-159.413) 485.487,-158.641 ; 484.896,-156.617 483.991,-155.712 478.923,-155.712 ; 485.028,-156.749 ccw(c485.488,-156.289) 485.488,-156.94 ; 485.488,-156.984 485.263,-156.984 ; 493.812,-85.98 493.818,-85.986 495.343,-85.986 495.387,-86.03 500.204,-86.03 500.303,-86.13 ; 498.271,277.566 cw(c499.117,276.72) 499.117,277.916 ; 498.44,277.735 cw(c498.993,277.183) 499.116,277.954 ; 498.525,279.978 497.62,280.884 492.552,280.884 ; 498.657,279.846 ccw(c499.117,280.306) 499.117,279.656 ; 499.117,279.611 498.892,279.611 ; 507.44,350.616 507.447,350.609 508.971,350.609 509.016,350.565 513.832,350.565 513.932,350.465 ; 518.003,-71.91 520.635,-71.91 ; 520.635,-71.942 520.635,-73.224 520.649,-73.237 ; 522.286,-71.942 522.427,-72.082 522.427,-73.364 ; 522.579,-71.942 528.573,-71.942 ; 531.632,364.685 534.264,364.685 ; 534.264,364.654 534.264,363.372 534.277,363.358 ; 535.915,364.654 536.055,364.513 536.055,363.231 ; 536.208,364.654 542.201,364.654 ; 289.605,-74.956 290.89,-73.671 290.89,-71.667 ; 289.605,-74.956 289.605,-73.968 ; 289.605,-74.956 289.605,-75.826 289.54,-75.762 289.54,-73.017 290.89,-71.667 ; 289.605,-73.968 289.605,-71.146 ; 289.605,-73.968 290.89,-72.683 ; 289.605,-71.146 289.605,-69.811 ; 289.605,-69.811 289.605,-69.049 290.429,-68.225 291.191,-68.225 291.217,-68.2 ; 289.605,-69.811 291.217,-68.2 ; 290.89,-72.683 290.89,-69.415 292.106,-68.2 ; 291.217,-68.2 292.106,-68.2 ; 300.589,-68.161 300.589,-68.225 301.097,-68.733 302.621,-68.733 ; 303.234,361.639 304.519,362.925 304.519,364.928 ; 303.234,361.639 303.234,362.627 ; 303.234,361.639 303.234,360.769 303.169,360.834 303.169,363.578 304.519,364.928 ; 303.234,362.627 303.234,365.449 ; 303.234,362.627 304.519,363.912 ; 303.234,365.449 303.234,366.784 ; 303.234,366.784 303.234,367.546 304.058,368.37 304.82,368.37 304.845,368.396 ; 303.234,366.784 304.845,368.396 ; 304.519,363.912 304.519,367.18 305.734,368.396 ; 304.845,368.396 305.734,368.396 ; 314.218,368.434 314.218,368.37 314.726,367.862 316.25,367.862 ; 322.179,-156.984 336.651,-156.984 337.923,-155.712 ; 335.808,279.611 350.28,279.611 351.552,280.884 ; 337.92,-161.946 339.837,-161.946 341.991,-159.792 343.331,-159.792 344.488,-158.635 344.037,-158.635 ; 337.92,-161.946 338.821,-161.946 341.61,-159.157 343.515,-159.157 344.037,-158.635 ; 337.92,-161.946 341.231,-158.635 344.037,-158.635 ; 337.923,-155.712 337.923,-156.105 338.816,-156.998 338.83,-156.984 344.263,-156.984 ; 351.549,274.649 353.466,274.649 355.62,276.803 356.96,276.803 358.117,277.96 357.666,277.96 ; 351.549,274.649 352.45,274.649 355.239,277.438 357.144,277.438 357.666,277.96 ; 351.549,274.649 354.86,277.96 357.666,277.96 ; 351.552,280.884 351.552,280.491 352.445,279.597 352.459,279.611 357.892,279.611 ; 430.605,-74.956 431.89,-73.671 431.89,-71.667 ; 430.605,-74.956 430.605,-73.968 ; 430.605,-74.956 430.605,-75.826 430.54,-75.762 430.54,-73.017 431.89,-71.667 ; 430.605,-73.968 430.605,-71.146 ; 430.605,-73.968 431.89,-72.683 ; 430.605,-71.146 430.605,-69.811 ; 430.605,-69.811 430.605,-69.049 431.429,-68.225 432.191,-68.225 432.217,-68.2 ; 430.605,-69.811 432.217,-68.2 ; 431.89,-72.683 431.89,-69.415 433.106,-68.2 ; 432.217,-68.2 433.106,-68.2 ; 441.589,-68.161 441.589,-68.225 442.097,-68.733 443.621,-68.733 ; 444.234,361.639 445.519,362.925 445.519,364.928 ; 444.234,361.639 444.234,362.627 ; 444.234,361.639 444.234,360.769 444.169,360.834 444.169,363.578 445.519,364.928 ; 444.234,362.627 444.234,365.449 ; 444.234,362.627 445.519,363.912 ; 444.234,365.449 444.234,366.784 ; 444.234,366.784 444.234,367.546 445.058,368.37 445.82,368.37 445.845,368.396 ; 444.234,366.784 445.845,368.396 ; 445.519,363.912 445.519,367.18 446.734,368.396 ; 445.845,368.396 446.734,368.396 ; 455.218,368.434 455.218,368.37 455.726,367.862 457.25,367.862 ; 463.179,-156.984 477.651,-156.984 478.923,-155.712 ; 476.808,279.611 491.28,279.611 492.552,280.884 ; 478.92,-161.946 480.837,-161.946 482.991,-159.792 484.331,-159.792 485.488,-158.635 485.037,-158.635 ; 478.92,-161.946 479.821,-161.946 482.61,-159.157 484.515,-159.157 485.037,-158.635 ; 478.92,-161.946 482.231,-158.635 485.037,-158.635 ; 478.923,-155.712 478.923,-156.105 479.816,-156.998 479.83,-156.984 485.263,-156.984 ; 492.549,274.649 494.466,274.649 496.62,276.803 497.96,276.803 499.117,277.96 498.666,277.96 ; 492.549,274.649 493.45,274.649 496.239,277.438 498.144,277.438 498.666,277.96 ; 492.549,274.649 495.86,277.96 498.666,277.96 ; 492.552,280.884 492.552,280.491 493.445,279.597 493.459,279.611 498.892,279.611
